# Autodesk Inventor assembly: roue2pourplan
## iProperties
Shininess: 64.0
Length Units: 11269
Angle Units: 11279
Time Units: 11290
Mass Units: 11283
Length Display Precision: 3
Angle Display Precision: 2
Compacted: True
Created: 2004-09
Part Number: roue2pourplan
Document SubType Name: Assembly
Designer: Administrateur
Density: 0.0
Volumn: 0.0
Area: 0.0
PropertySet Name: Model Information
Control State: 0
Master: False
Checked Out: False
Author: Administrateur
